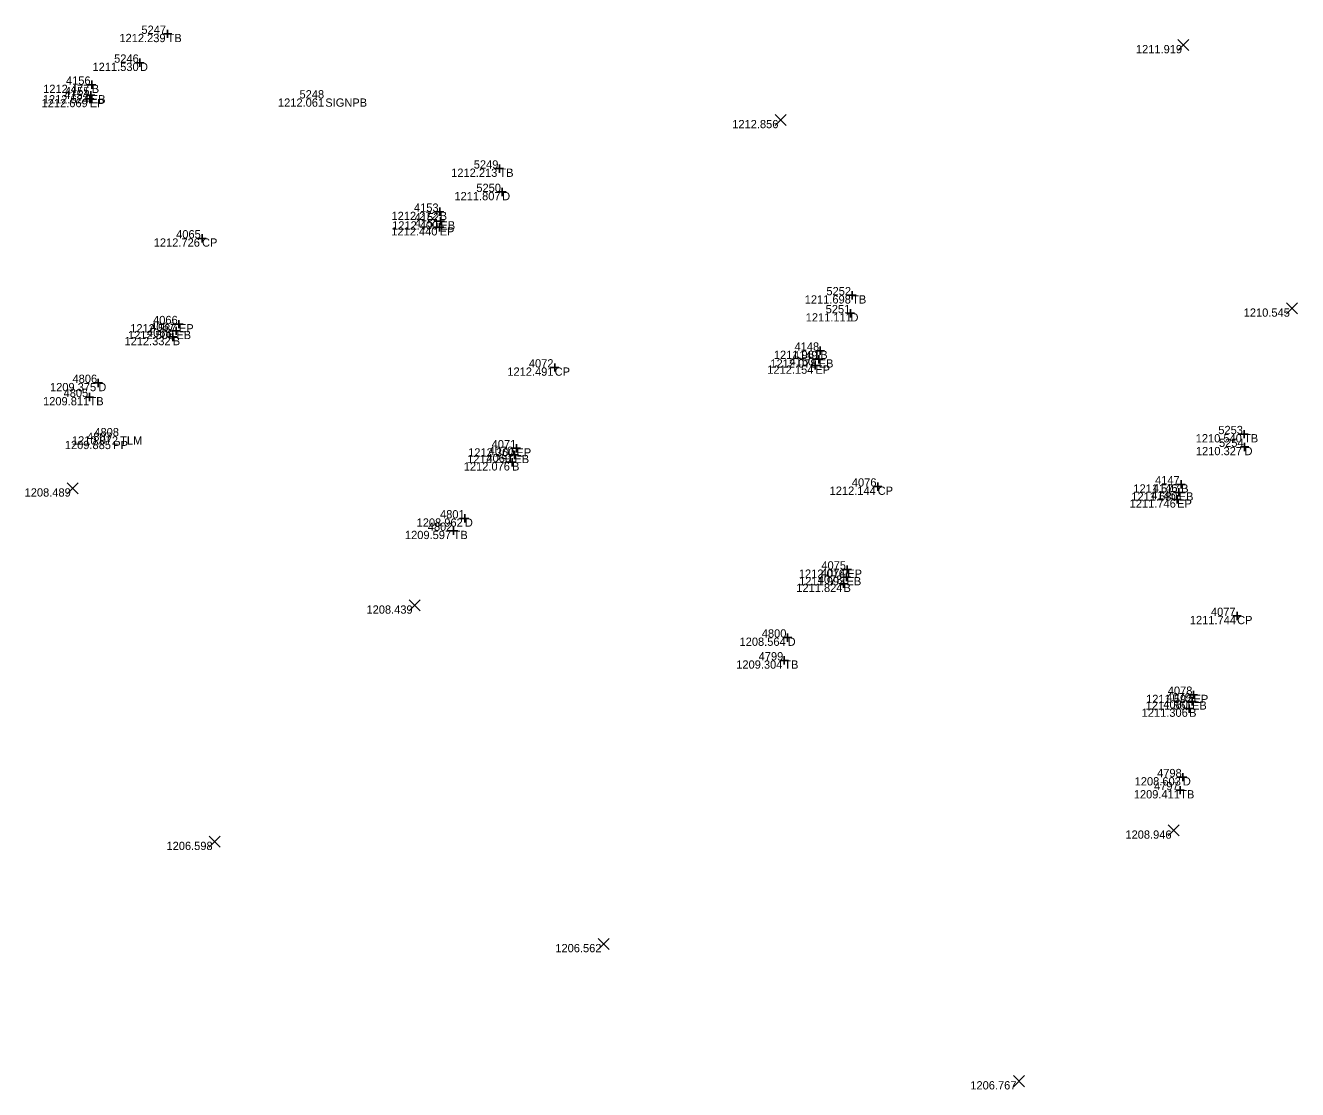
# Model space of a CAD drawing. Extents: x 2044997 to 2050342, y 455233 to 458054.
# Drawn here: x 2048105.9 to 2048259.7, y 456712.7 to 456841.4 of the extents above; entities that cross this region are included whole.
import ezdxf

# ---------------------------------------------------------------- set-up
doc = ezdxf.new("R2010")
doc.units = 0
for name, color, linetype in [('SV_X_Random_Point', 7, 'Continuous'), ('SV_X_Shot_Marker', 7, 'Continuous'), ('SV_X_Text_Comment', 7, 'Continuous'), ('SV_X_Text_Elevation', 7, 'Continuous'), ('SV_X_Text_Name', 7, 'Continuous')]:
    doc.layers.add(name, color=color, linetype=linetype)

msp = doc.modelspace()

# ---------------------------------------------------------------- linework, layer by layer
at = {"layer": 'SV_X_Random_Point'}
for p, q in [((2048245.19, 456838.38), (2048246.52, 456839.71)), ((2048245.19, 456839.71), (2048246.52, 456838.38)), ((2048196.52, 456829.32), (2048197.85, 456830.65)), ((2048196.52, 456830.65), (2048197.85, 456829.32)), ((2048258.35, 456806.53), (2048259.68, 456807.87)), ((2048258.35, 456807.87), (2048259.68, 456806.53)), ((2048110.94, 456784.79), (2048112.27, 456786.12)), ((2048110.94, 456786.12), (2048112.27, 456784.79)), ((2048152.27, 456770.62), (2048153.61, 456771.95)), ((2048152.27, 456771.95), (2048153.61, 456770.62)), ((2048244.05, 456743.42), (2048245.38, 456744.75)), ((2048244.05, 456744.75), (2048245.38, 456743.42)), ((2048128.11, 456742.05), (2048129.44, 456743.38)), ((2048128.11, 456743.38), (2048129.44, 456742.05)), ((2048175.12, 456729.68), (2048176.45, 456731.01)), ((2048175.12, 456731.01), (2048176.45, 456729.68)), ((2048225.33, 456713.09), (2048226.67, 456714.43)), ((2048225.33, 456714.43), (2048226.67, 456713.09))]:
    msp.add_line(p, q, dxfattribs=at)
at = {"layer": 'SV_X_Shot_Marker'}
for p, q in [((2048122.57, 456840.4), (2048123.57, 456840.4)), ((2048123.07, 456840.9), (2048123.07, 456839.9)), ((2048123.07, 456840.4), (2048123.07, 456840.4)), ((2048119.73, 456837.41), (2048119.73, 456836.41)), ((2048119.23, 456836.91), (2048120.23, 456836.91)), ((2048119.73, 456836.91), (2048119.73, 456836.91)), ((2048113.41, 456834.25), (2048114.41, 456834.25)), ((2048113.91, 456834.75), (2048113.91, 456833.75)), ((2048113.91, 456834.25), (2048113.91, 456834.25)), ((2048113.29, 456832.99), (2048114.29, 456832.99)), ((2048113.66, 456833.03), (2048113.66, 456832.03)), ((2048113.79, 456833.49), (2048113.79, 456832.49)), ((2048113.79, 456832.99), (2048113.79, 456832.99)), ((2048113.16, 456832.53), (2048114.16, 456832.53)), ((2048113.66, 456832.53), (2048113.66, 456832.53)), ((2048162.69, 456824.11), (2048163.69, 456824.11)), ((2048163.19, 456824.61), (2048163.19, 456823.61)), ((2048163.19, 456824.11), (2048163.19, 456824.11)), ((2048163.02, 456821.28), (2048164.02, 456821.28)), ((2048163.52, 456821.78), (2048163.52, 456820.78)), ((2048163.52, 456821.28), (2048163.52, 456821.28)), ((2048155.47, 456818.89), (2048156.47, 456818.89)), ((2048155.97, 456819.39), (2048155.97, 456818.39)), ((2048155.97, 456818.89), (2048155.97, 456818.89)), ((2048155.56, 456817.74), (2048156.56, 456817.74)), ((2048155.96, 456817.52), (2048155.96, 456816.52)), ((2048156.06, 456818.24), (2048156.06, 456817.24)), ((2048156.06, 456817.74), (2048156.06, 456817.74)), ((2048127.24, 456816.17), (2048127.24, 456815.17)), ((2048155.46, 456817.02), (2048156.46, 456817.02)), ((2048155.96, 456817.02), (2048155.96, 456817.02)), ((2048126.74, 456815.67), (2048127.74, 456815.67)), ((2048127.24, 456815.67), (2048127.24, 456815.67)), ((2048205.33, 456808.79), (2048206.33, 456808.79)), ((2048205.83, 456809.29), (2048205.83, 456808.29)), ((2048205.83, 456808.79), (2048205.83, 456808.79)), ((2048205.13, 456806.62), (2048206.13, 456806.62)), ((2048205.63, 456807.12), (2048205.63, 456806.12)), ((2048205.63, 456806.62), (2048205.63, 456806.62)), ((2048123.94, 456805.3), (2048124.94, 456805.3)), ((2048124.13, 456804.99), (2048124.13, 456803.99)), ((2048124.44, 456805.8), (2048124.44, 456804.8)), ((2048124.44, 456805.3), (2048124.44, 456805.3)), ((2048123.2, 456803.75), (2048124.2, 456803.75)), ((2048123.63, 456804.49), (2048124.63, 456804.49)), ((2048123.7, 456804.25), (2048123.7, 456803.25)), ((2048123.7, 456803.75), (2048123.7, 456803.75)), ((2048124.13, 456804.49), (2048124.13, 456804.49)), ((2048201.48, 456802.09), (2048202.48, 456802.09)), ((2048201.98, 456802.59), (2048201.98, 456801.59)), ((2048201.98, 456802.09), (2048201.98, 456802.09)), ((2048169.87, 456800.56), (2048169.87, 456799.56)), ((2048201.29, 456801.05), (2048202.29, 456801.05)), ((2048201.38, 456800.8), (2048201.38, 456799.8)), ((2048201.79, 456801.55), (2048201.79, 456800.55)), ((2048201.79, 456801.05), (2048201.79, 456801.05)), ((2048169.37, 456800.06), (2048170.37, 456800.06)), ((2048169.87, 456800.06), (2048169.87, 456800.06)), ((2048200.88, 456800.3), (2048201.88, 456800.3)), ((2048201.38, 456800.3), (2048201.38, 456800.3)), ((2048114.2, 456798.19), (2048115.2, 456798.19)), ((2048114.7, 456798.69), (2048114.7, 456797.69)), ((2048114.7, 456798.19), (2048114.7, 456798.19)), ((2048113.13, 456796.48), (2048114.13, 456796.48)), ((2048113.63, 456796.98), (2048113.63, 456795.98)), ((2048113.63, 456796.48), (2048113.63, 456796.48)), ((2048252.71, 456792), (2048253.71, 456792)), ((2048253.21, 456792.5), (2048253.21, 456791.5)), ((2048253.21, 456792), (2048253.21, 456792)), ((2048164.75, 456790.29), (2048165.75, 456790.29)), ((2048165, 456789.99), (2048165, 456788.99)), ((2048165.25, 456790.79), (2048165.25, 456789.79)), ((2048165.25, 456790.29), (2048165.25, 456790.29)), ((2048252.77, 456790.45), (2048253.77, 456790.45)), ((2048253.27, 456790.95), (2048253.27, 456789.95)), ((2048253.27, 456790.45), (2048253.27, 456790.45)), ((2048164.22, 456788.6), (2048165.22, 456788.6)), ((2048164.5, 456789.49), (2048165.5, 456789.49)), ((2048164.72, 456789.1), (2048164.72, 456788.1)), ((2048164.72, 456788.6), (2048164.72, 456788.6)), ((2048165, 456789.49), (2048165, 456789.49)), ((2048208.42, 456785.66), (2048209.42, 456785.66)), ((2048208.92, 456786.16), (2048208.92, 456785.16)), ((2048208.92, 456785.66), (2048208.92, 456785.66)), ((2048244.81, 456784.96), (2048245.81, 456784.96)), ((2048245.11, 456785.93), (2048246.11, 456785.93)), ((2048245.31, 456785.46), (2048245.31, 456784.46)), ((2048245.31, 456784.96), (2048245.31, 456784.96)), ((2048245.61, 456786.43), (2048245.61, 456785.43)), ((2048245.61, 456785.93), (2048245.61, 456785.93)), ((2048244.62, 456784.11), (2048245.62, 456784.11)), ((2048245.12, 456784.61), (2048245.12, 456783.61)), ((2048245.12, 456784.11), (2048245.12, 456784.11)), ((2048159.01, 456782.31), (2048159.01, 456781.31)), ((2048157.65, 456780.81), (2048157.65, 456779.81)), ((2048158.51, 456781.81), (2048159.51, 456781.81)), ((2048159.01, 456781.81), (2048159.01, 456781.81)), ((2048157.15, 456780.31), (2048158.15, 456780.31)), ((2048157.65, 456780.31), (2048157.65, 456780.31)), ((2048205.24, 456776.13), (2048205.24, 456775.13)), ((2048204.65, 456774.72), (2048205.65, 456774.72)), ((2048204.74, 456775.63), (2048205.74, 456775.63)), ((2048204.79, 456774.41), (2048204.79, 456773.41)), ((2048205.15, 456775.22), (2048205.15, 456774.22)), ((2048205.15, 456774.72), (2048205.15, 456774.72)), ((2048205.24, 456775.63), (2048205.24, 456775.63)), ((2048204.29, 456773.91), (2048205.29, 456773.91)), ((2048204.79, 456773.91), (2048204.79, 456773.91)), ((2048251.87, 456770.02), (2048252.87, 456770.02)), ((2048252.37, 456770.52), (2048252.37, 456769.52)), ((2048252.37, 456770.02), (2048252.37, 456770.02)), ((2048197.53, 456767.4), (2048198.53, 456767.4)), ((2048198.03, 456767.9), (2048198.03, 456766.9)), ((2048198.03, 456767.4), (2048198.03, 456767.4)), ((2048197.63, 456765.14), (2048197.63, 456764.14)), ((2048197.13, 456764.64), (2048198.13, 456764.64)), ((2048197.63, 456764.64), (2048197.63, 456764.64)), ((2048246.6, 456760.48), (2048247.6, 456760.48)), ((2048247.1, 456760.98), (2048247.1, 456759.98)), ((2048247.1, 456760.48), (2048247.1, 456760.48)), ((2048246.07, 456758.82), (2048247.07, 456758.82)), ((2048246.42, 456759.69), (2048247.42, 456759.69)), ((2048246.57, 456759.32), (2048246.57, 456758.32)), ((2048246.57, 456758.82), (2048246.57, 456758.82)), ((2048246.92, 456760.19), (2048246.92, 456759.19)), ((2048246.92, 456759.69), (2048246.92, 456759.69)), ((2048245.31, 456750.52), (2048246.31, 456750.52)), ((2048245.81, 456751.02), (2048245.81, 456750.02)), ((2048245.81, 456750.52), (2048245.81, 456750.52)), ((2048244.99, 456748.95), (2048245.99, 456748.95)), ((2048245.49, 456749.45), (2048245.49, 456748.45)), ((2048245.49, 456748.95), (2048245.49, 456748.95))]:
    msp.add_line(p, q, dxfattribs=at)

# ---------------------------------------------------------------- texts
at = {"layer": 'SV_X_Text_Comment'}
for s, p in [('TB', (2048123.07, 456839.4)), ('D', (2048119.73, 456835.91)), ('B', (2048113.91, 456833.25)), ('EB', (2048113.79, 456831.99)), ('EP', (2048113.66, 456831.53)), ('SIGNPB', (2048142.14, 456831.59)), ('TB', (2048163.19, 456823.11)), ('D', (2048163.52, 456820.28)), ('B', (2048155.97, 456817.89)), ('EB', (2048156.06, 456816.74)), ('EP', (2048155.96, 456816.02)), ('CP', (2048127.24, 456814.67)), ('TB', (2048205.83, 456807.79)), ('D', (2048205.63, 456805.62)), ('EP', (2048124.44, 456804.3)), ('B', (2048123.7, 456802.75)), ('EB', (2048124.13, 456803.49)), ('B', (2048201.98, 456801.09)), ('EB', (2048201.79, 456800.05)), ('CP', (2048169.87, 456799.06)), ('EP', (2048201.38, 456799.3)), ('D', (2048114.7, 456797.19)), ('TB', (2048113.63, 456795.48)), ('PP', (2048116.5, 456790.19)), ('TLM', (2048117.34, 456790.74)), ('TB', (2048253.21, 456791)), ('EP', (2048165.25, 456789.29)), ('D', (2048253.27, 456789.45)), ('B', (2048164.72, 456787.6)), ('EB', (2048165, 456788.49)), ('CP', (2048208.92, 456784.66)), ('EB', (2048245.31, 456783.96)), ('B', (2048245.61, 456784.93)), ('EP', (2048245.12, 456783.11)), ('D', (2048159.01, 456780.81)), ('TB', (2048157.65, 456779.31)), ('EB', (2048205.15, 456773.72)), ('EP', (2048205.24, 456774.63)), ('B', (2048204.79, 456772.91)), ('CP', (2048252.37, 456769.02)), ('D', (2048198.03, 456766.4)), ('TB', (2048197.63, 456763.64)), ('EP', (2048247.1, 456759.48)), ('B', (2048246.57, 456757.82)), ('EB', (2048246.92, 456758.69)), ('D', (2048245.81, 456749.52)), ('TB', (2048245.49, 456747.95))]:
    msp.add_text(s, height=1, dxfattribs=at).set_placement(p)
at = {"layer": 'SV_X_Text_Elevation'}
for s, p in [('1212.239', (2048117.25, 456839.4)), ('1211.919', (2048240.14, 456838.05)), ('1211.530', (2048114, 456835.91)), ('1212.477', (2048108.03, 456833.25)), ('1212.624', (2048107.99, 456831.99)), ('1212.669', (2048107.84, 456831.53)), ('1212.061', (2048136.42, 456831.59)), ('1212.856', (2048191.34, 456828.99)), ('1212.213', (2048157.36, 456823.11)), ('1211.807', (2048157.75, 456820.28)), ('1212.272', (2048150.14, 456817.89)), ('1212.400', (2048150.22, 456816.74)), ('1212.440', (2048150.12, 456816.02)), ('1212.726', (2048121.4, 456814.67)), ('1211.698', (2048200.1, 456807.79)), ('1211.111', (2048200.22, 456805.62)), ('1210.545', (2048253.17, 456806.2)), ('1212.587', (2048118.56, 456804.3)), ('1212.332', (2048117.86, 456802.75)), ('1212.506', (2048118.29, 456803.49)), ('1211.961', (2048196.37, 456801.09)), ('1212.078', (2048195.95, 456800.05)), ('1212.491', (2048164.15, 456799.06)), ('1212.154', (2048195.57, 456799.3)), ('1209.375', (2048108.86, 456797.19)), ('1209.811', (2048108.02, 456795.48)), ('1209.885', (2048110.65, 456790.19)), ('1210.072', (2048111.51, 456790.74)), ('1210.540', (2048247.37, 456791)), ('1212.360', (2048159.41, 456789.29)), ('1210.327', (2048247.39, 456789.45)), ('1212.076', (2048158.88, 456787.6)), ('1212.251', (2048159.29, 456788.49)), ('1208.489', (2048105.79, 456784.45)), ('1212.144', (2048203.11, 456784.66)), ('1211.680', (2048239.58, 456783.96)), ('1211.577', (2048239.83, 456784.93)), ('1211.746', (2048239.38, 456783.11)), ('1208.962', (2048153.18, 456780.81)), ('1209.597', (2048151.77, 456779.31)), ('1212.016', (2048199.39, 456774.63)), ('1211.993', (2048199.42, 456773.72)), ('1211.824', (2048199.08, 456772.91)), ('1208.439', (2048147.12, 456770.29)), ('1211.744', (2048246.66, 456769.02)), ('1208.564', (2048192.22, 456766.4)), ('1209.304', (2048191.82, 456763.64)), ('1211.592', (2048241.37, 456759.48)), ('1211.306', (2048240.83, 456757.82)), ('1211.561', (2048241.31, 456758.69)), ('1208.603', (2048239.99, 456749.52)), ('1209.411', (2048239.88, 456747.95)), ('1208.946', (2048238.87, 456743.08)), ('1206.598', (2048122.94, 456741.71)), ('1206.562', (2048169.95, 456729.35)), ('1206.767', (2048220.12, 456712.76))]:
    msp.add_text(s, height=1, dxfattribs=at).set_placement(p)
at = {"layer": 'SV_X_Text_Name'}
for s, p in [('5247', (2048119.91, 456840.4)), ('5246', (2048116.61, 456836.91)), ('4156', (2048110.79, 456834.25)), ('4154', (2048110.57, 456832.53)), ('4155', (2048110.66, 456832.99)), ('5248', (2048139.02, 456832.59)), ('5249', (2048160.09, 456824.11)), ('5250', (2048160.4, 456821.28)), ('4153', (2048152.86, 456818.89)), ('4152', (2048152.94, 456817.74)), ('4151', (2048152.96, 456817.02)), ('4065', (2048124.11, 456815.67)), ('5252', (2048202.72, 456808.79)), ('5251', (2048202.63, 456806.62)), ('4067', (2048120.97, 456804.49)), ('4066', (2048121.32, 456805.3)), ('4068', (2048120.58, 456803.75)), ('4149', (2048198.69, 456801.05)), ('4148', (2048198.87, 456802.09)), ('4072', (2048166.75, 456800.06)), ('4150', (2048198.26, 456800.3)), ('4806', (2048111.58, 456798.19)), ('4805', (2048110.5, 456796.48)), ('4808', (2048114.22, 456791.74)), ('5253', (2048250.1, 456792)), ('4807', (2048113.34, 456791.19)), ('4071', (2048162.25, 456790.29)), ('5254', (2048250.18, 456790.45)), ('4069', (2048161.62, 456788.6)), ('4070', (2048161.88, 456789.49)), ('4076', (2048205.8, 456785.66)), ('4147', (2048242.45, 456785.93)), ('4145', (2048241.99, 456784.11)), ('4146', (2048242.19, 456784.96)), ('4801', (2048156.01, 456781.81)), ('4802', (2048154.53, 456780.31)), ('4074', (2048202.06, 456774.72)), ('4075', (2048202.11, 456775.63)), ('4073', (2048201.68, 456773.91)), ('4077', (2048249.21, 456770.02)), ('4800', (2048194.91, 456767.4)), ('4799', (2048194.53, 456764.64)), ('4079', (2048243.82, 456759.69)), ('4078', (2048243.99, 456760.48)), ('4080', (2048243.45, 456758.82)), ('4798', (2048242.7, 456750.52)), ('4797', (2048242.33, 456748.95))]:
    msp.add_text(s, height=1, dxfattribs=at).set_placement(p)

doc.saveas('drawing.dxf')
